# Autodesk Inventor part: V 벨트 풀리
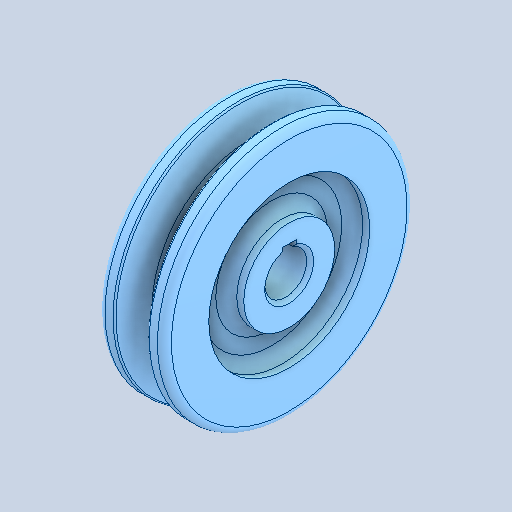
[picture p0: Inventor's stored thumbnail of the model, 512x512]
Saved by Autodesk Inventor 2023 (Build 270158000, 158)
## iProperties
Created: 2026-06
Part Number: V 벨트 풀리
Material: 강철, 주조
Document SubType Name: Modeling
Designer: home
Density: 7.85 g/cm^3
Appearance: 기본값
Author: jhkim
Sending System: Autodesk Inventor 2027
Preprocessor: ST-DEVELOPER v20.1
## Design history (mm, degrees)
feature "솔리드1"
node "솔리드2"
